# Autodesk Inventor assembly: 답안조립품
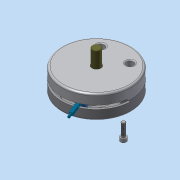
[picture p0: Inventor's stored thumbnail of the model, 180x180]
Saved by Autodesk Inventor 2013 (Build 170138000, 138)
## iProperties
Created: 2015-04
Part Number: 답안조립품
Document SubType Name: Assembly
Designer: Administrator
Author: Administrator
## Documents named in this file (10)
- C:\Users\Administrator\Desktop\450406V1011\답안조립품.iam
- C:\Users\Administrator\Desktop\450406V1011\본체.ipt
- C:\Users\Administrator\Desktop\450406V1011\M 10 x 35.ipt
- C:\Users\Administrator\Desktop\450406V1011\덮개.ipt
- C:\Users\Administrator\Desktop\450406V1011\멈춤링.ipt
- C:\Users\Administrator\Desktop\450406V1011\베어링62_22.ipt
- C:\Users\Administrator\Desktop\450406V1011\슬라이더.ipt
- C:\Users\Administrator\Desktop\450406V1011\슬라이더2.ipt
- C:\Users\Administrator\Desktop\450406V1011\축.ipt
- C:\Users\Administrator\Desktop\450406V1011\평행핀.ipt
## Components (2 placed, 1 different names)
1. M 10 x 35:1
2. M 10 x 35:2 — 플러쉬:1
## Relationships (1: Flush 1)
- 플러쉬:1 [Flush]: M 10 x 35:2
